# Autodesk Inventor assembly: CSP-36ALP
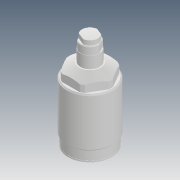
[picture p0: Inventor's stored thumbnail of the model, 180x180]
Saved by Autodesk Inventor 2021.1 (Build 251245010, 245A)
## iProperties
Created: 2019-01
Part Number: CSP-36ALP
Description: STEP AP203
Document SubType Name: Assembly
Designer: user
Title: CSP-36ALP.STEP
Revision Number: ÈÎºÎ
Sending System: SolidWorks 2014
Preprocessor: SwSTEP 2.0
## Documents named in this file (4)
- D:\Vault_2016\Projekty\Clamptek\Hydraulic\CSP-P-K\CSP-36KP\Inventor\CSP-36ALP\CSP-36ALP.iam
- D:\Vault_2016\Projekty\Clamptek\Hydraulic\CSP-P-K\CSP-36KP\Inventor\CSP-36ALP\CSP-036-P±¾Ìå£¨ÉÏÉý£©.ipt
- D:\Vault_2016\Projekty\Clamptek\Hydraulic\CSP-P-K\CSP-36KP\Inventor\CSP-36ALP\CSP-036»îÈû¸Ë.ipt
- D:\Vault_2016\Projekty\Clamptek\Hydraulic\CSP-P-K\CSP-36KP\Inventor\CSP-36ALP\CSP-036Ô²Í·ÂÝË¨.ipt
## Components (3 placed, 3 different names)
1. CSP-036-P±¾Ìå£¨ÉÏÉý£©_1
2. CSP-036»îÈû¸Ë_2
3. CSP-036Ô²Í·ÂÝË¨_3
